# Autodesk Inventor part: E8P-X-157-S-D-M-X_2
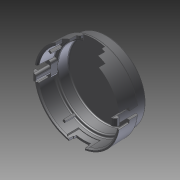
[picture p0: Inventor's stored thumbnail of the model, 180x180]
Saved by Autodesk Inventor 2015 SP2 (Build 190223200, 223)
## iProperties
Created: 2012-07
Part Number: E8P-X-157-S-D-M-X_2
Material: Allgemein
Document SubType Name: Modeling
Designer: rYan
Density: 1 g/cm^3
Mass: 1.04278 g
Surface Area: 25.6207 cm^2
Volume: 1.04278 cm^3
Appearance: Vorgabe
Author: rYan
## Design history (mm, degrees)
node "E8P-X-157-S-D-M-X_21"
node "E8P-X-157-S-D-M-X_2"
node "Basis1"
